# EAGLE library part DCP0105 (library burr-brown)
DC/DC Converters Miniature 5V Input, 1W Isolated Unregulated
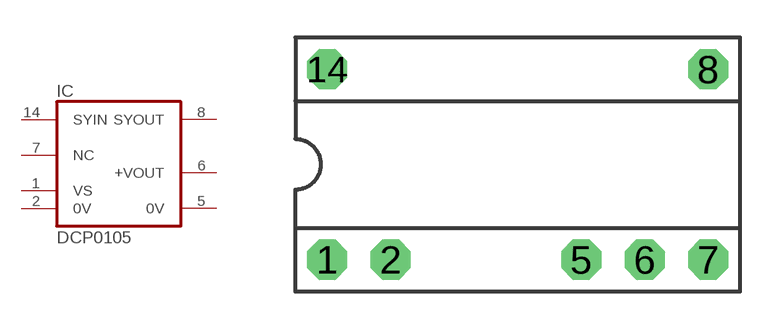
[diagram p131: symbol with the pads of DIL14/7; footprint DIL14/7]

Designator prefix IC

## DCP0105P (MPN: DCP010512BP-U; OC_FARNELL: 1461015; OC_NEWARK: 61M5777)  [DIL14/7]
1  VS  pwr
2  0V  pwr
5  0V  pwr
6  +VOUT  pwr
7  NC  nc
8  SYOUT  out
14  SYIN  in

## Footprint DIL14/7 (pad centres in mm)
Dual In Line
drill 0.813 pad 1.6 octagon: 1 -7.62,-3.81; 2 -5.08,-3.81; 5 2.54,-3.81; 6 5.08,-3.81; 7 7.62,-3.81; 8 7.62,3.81; 14 -7.62,3.81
